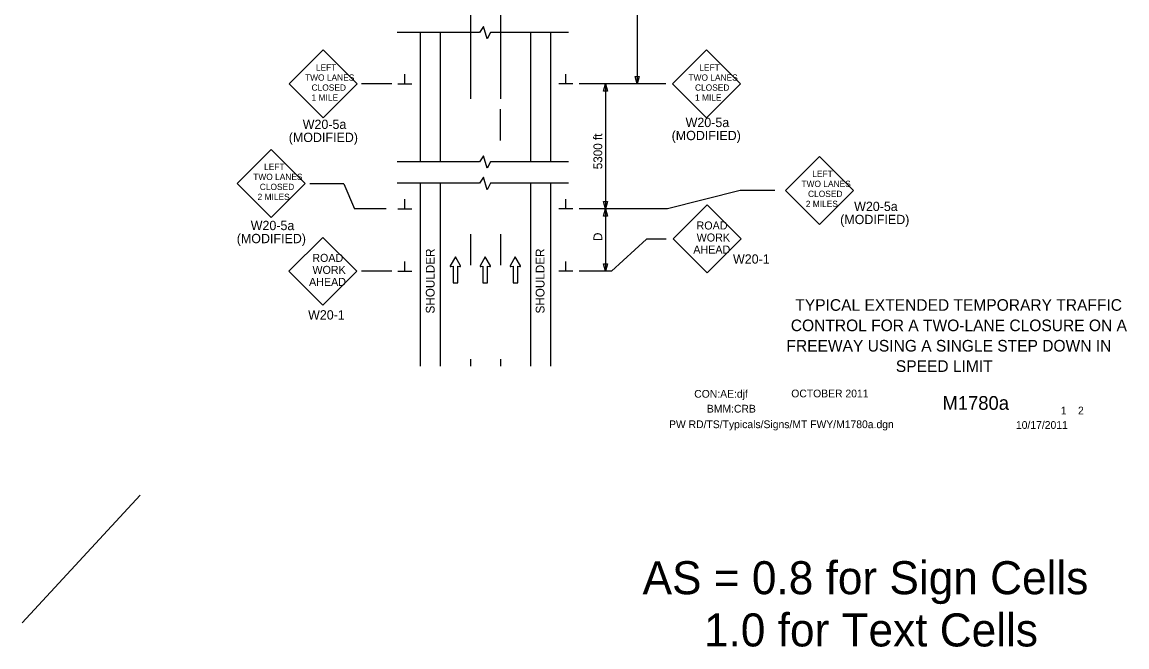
# Model space of a CAD drawing. Extents: x 16553 to 18478, y 5759 to 7026.
# Drawn here: x 16553 to 17437, y 5759 to 6259 of the extents above; entities that cross this region are included whole.
import ezdxf

# ---------------------------------------------------------------- set-up
doc = ezdxf.new("R2010")
doc.units = 0
for name, color, linetype in [('ALI_LEGAL_EX', 7, 'Continuous'), ('BORDER', 7, 'Continuous'), ('BORDER_SIGNAL_WO', 7, 'Continuous'), ('MT_SCRATCH_LEVEL_E', 7, 'Continuous'), ('PAVT_EDGE_EX', 7, 'Continuous'), ('TRAFFIC_SIGNS_PR', 7, 'Continuous'), ('TYPICAL_TEXT_DIMEN_PR', 7, 'Continuous')]:
    doc.layers.add(name, color=color, linetype=linetype)

msp = doc.modelspace()

# ---------------------------------------------------------------- linework, layer by layer
at = {"layer": 'ALI_LEGAL_EX'}
for p, q in [((16911.66, 7026.35), (16911.66, 6197.16)), ((16935.66, 7026.35), (16935.66, 6197.16)), ((16935.66, 7026.35), (16935.66, 6197.16))]:
    msp.add_line(p, q, dxfattribs=at)
for points in [[(16911.66, 6226.35), (16911.66, 6201.35)], [(16935.66, 6226.35), (16935.66, 6201.35)], [(16935.66, 6163.99), (16935.66, 6188.99)], [(16911.66, 6088.99), (16911.66, 6063.99)], [(16935.66, 6088.99), (16935.66, 6063.99)], [(16911.66, 5988.99), (16911.66, 5983.43)], [(16935.66, 5988.99), (16935.66, 5983.43)]]:
    msp.add_lwpolyline(points, dxfattribs=at)
at = {"layer": 'MT_SCRATCH_LEVEL_E'}
for p, q in [((16899.66, 6070.89), (16895.55, 6063.65)), ((16903.81, 6063.65), (16899.66, 6070.89)), ((16923.57, 6070.89), (16919.46, 6063.65)), ((16927.71, 6063.65), (16923.57, 6070.89)), ((16947.62, 6070.89), (16943.51, 6063.65)), ((16951.77, 6063.65), (16947.62, 6070.89)), ((16896.03, 6062.97), (16897.81, 6063.28)), ((16897.81, 6063.28), (16897.81, 6050.03)), ((16901.55, 6050.03), (16901.55, 6063.28)), ((16901.55, 6063.28), (16903.33, 6062.97)), ((16919.94, 6062.97), (16921.72, 6063.28)), ((16921.72, 6063.28), (16921.72, 6050.03)), ((16925.46, 6050.03), (16925.46, 6063.28)), ((16925.46, 6063.28), (16927.24, 6062.97)), ((16943.99, 6062.97), (16945.77, 6063.28)), ((16945.77, 6063.28), (16945.77, 6050.03)), ((16949.51, 6050.03), (16949.51, 6063.28)), ((16949.51, 6063.28), (16951.29, 6062.97)), ((16897.81, 6050.03), (16901.55, 6050.03)), ((16921.72, 6050.03), (16925.46, 6050.03)), ((16945.77, 6050.03), (16949.51, 6050.03))]:
    msp.add_line(p, q, dxfattribs=at)
for centre, start, end in [((16895.96, 6063.43), 150.42484, 279.96381), ((16903.4, 6063.43), 260.03619, 29.77312), ((16919.86, 6063.43), 150.42484, 279.96381), ((16927.3, 6063.43), 260.03619, 29.77312), ((16943.92, 6063.43), 150.42484, 279.96381), ((16951.36, 6063.43), 260.03619, 29.77312)]:
    msp.add_arc(centre, 0.463, start, end, dxfattribs=at)
at = {"layer": 'PAVT_EDGE_EX'}
for p, q in [((16871.66, 6250.21), (16871.66, 6146.79)), ((16887.66, 6250.21), (16887.66, 6146.8)), ((16959.66, 6250.21), (16959.66, 6146.8)), ((16975.66, 6250.21), (16975.66, 6146.8)), ((16959.66, 6226.79), (16959.66, 6223.96)), ((16871.66, 6129.66), (16871.66, 5983.43)), ((16887.66, 6129.66), (16887.66, 5983.43)), ((16959.66, 6129.66), (16959.66, 5983.43)), ((16975.66, 6129.66), (16975.66, 5983.43))]:
    msp.add_line(p, q, dxfattribs=at)
at = {"layer": 'TRAFFIC_SIGNS_PR'}
for p, q in [((16793.87, 6236.42), (16766.69, 6209.23)), ((16821.06, 6209.23), (16793.87, 6236.42)), ((17100.47, 6236.41), (17073.29, 6209.23)), ((17127.66, 6209.23), (17100.47, 6236.41)), ((16766.69, 6209.23), (16793.87, 6182.05)), ((16793.87, 6182.05), (16821.06, 6209.23)), ((17073.29, 6209.23), (17100.47, 6182.04)), ((17100.47, 6182.04), (17127.66, 6209.23)), ((16752.46, 6156.65), (16725.27, 6129.46)), ((16779.65, 6129.46), (16752.46, 6156.65)), ((17190.86, 6151.08), (17163.67, 6123.89)), ((17218.05, 6123.89), (17190.86, 6151.08)), ((16725.27, 6129.46), (16752.46, 6102.27)), ((16752.46, 6102.27), (16779.65, 6129.46)), ((17163.67, 6123.89), (17190.86, 6096.7)), ((17190.86, 6096.7), (17218.05, 6123.89)), ((17101.01, 6112.28), (17073.82, 6085.1)), ((17128.2, 6085.1), (17101.01, 6112.28)), ((16793.75, 6086.37), (16766.6, 6059.22)), ((16820.9, 6059.22), (16793.75, 6086.37)), ((17073.82, 6085.1), (17101.01, 6057.91)), ((17101.01, 6057.91), (17128.2, 6085.1)), ((16766.6, 6059.22), (16793.75, 6032.06)), ((16793.75, 6032.06), (16820.9, 6059.22))]:
    msp.add_line(p, q, dxfattribs=at)
at = {"layer": 'TYPICAL_TEXT_DIMEN_PR'}
for p, q in [((17045.1, 6561.07), (17045.1, 6209.23)), ((16922.27, 6255.01), (16919.01, 6250.21)), ((16925.01, 6245.07), (16922.27, 6255.01)), ((16919.01, 6250.21), (16853.07, 6250.21)), ((16927.75, 6250.21), (16925.01, 6245.07)), ((16990.08, 6250.21), (16927.75, 6250.21)), ((16859.29, 6209.23), (16859.29, 6217.01)), ((16988.04, 6209.23), (16988.04, 6217.01)), ((17045.1, 6209.23), (17043.53, 6215.09)), ((17043.53, 6215.09), (17045.1, 6215.09)), ((17045.1, 6215.09), (17046.67, 6215.09)), ((17046.67, 6215.09), (17045.1, 6209.23)), ((16848.86, 6209.23), (16824.56, 6209.23)), ((16853.66, 6209.23), (16864.91, 6209.23)), ((16993.66, 6209.23), (16982.41, 6209.23)), ((17067.96, 6209.23), (16998.66, 6209.23)), ((17018.09, 6203.36), (17019.66, 6209.23)), ((17019.66, 6203.36), (17018.09, 6203.36)), ((17019.66, 6209.23), (17019.66, 6109.23)), ((17019.66, 6209.23), (17021.24, 6203.36)), ((17021.24, 6203.36), (17019.66, 6203.36)), ((16922.27, 6151.59), (16919.01, 6146.79)), ((16925.01, 6141.65), (16922.27, 6151.59)), ((16919.01, 6146.79), (16853.07, 6146.79)), ((16927.75, 6146.79), (16925.01, 6141.65)), ((16990.08, 6146.79), (16927.75, 6146.79)), ((16922.27, 6134.45), (16919.01, 6129.65)), ((16925.01, 6124.51), (16922.27, 6134.45)), ((16810.37, 6129.13), (16783.2, 6129.13)), ((16810.37, 6129.13), (16819.13, 6109.23)), ((16919.01, 6129.65), (16853.07, 6129.65)), ((16927.75, 6129.65), (16925.01, 6124.51)), ((16990.08, 6129.65), (16927.75, 6129.65)), ((17127.51, 6123.89), (17069.24, 6109.23)), ((17155.1, 6123.89), (17127.51, 6123.89)), ((16859.29, 6109.23), (16859.29, 6117.01)), ((16988.04, 6109.23), (16988.04, 6117.01)), ((17019.66, 6109.23), (17018.09, 6115.09)), ((17018.09, 6115.09), (17019.66, 6115.09)), ((17019.66, 6115.09), (17021.24, 6115.09)), ((17021.24, 6115.09), (17019.66, 6109.23)), ((16844.35, 6109.23), (16819.13, 6109.23)), ((16853.66, 6109.23), (16864.91, 6109.23)), ((16993.66, 6109.23), (16982.41, 6109.23)), ((17069.24, 6109.23), (16998.66, 6109.23)), ((17018.09, 6103.36), (17019.66, 6109.23)), ((17019.66, 6109.23), (17019.66, 6059.23)), ((17019.66, 6109.23), (17021.24, 6103.36)), ((17019.66, 6103.36), (17018.09, 6103.36)), ((17021.24, 6103.36), (17019.66, 6103.36)), ((17052.49, 6085.03), (17024.66, 6059.23)), ((17068.18, 6085.03), (17052.49, 6085.03)), ((16859.29, 6059.23), (16859.29, 6067.01)), ((16988.04, 6059.23), (16988.04, 6067.01)), ((17019.66, 6059.23), (17018.09, 6065.09)), ((17018.09, 6065.09), (17019.66, 6065.09)), ((17019.66, 6065.09), (17021.24, 6065.09)), ((17021.24, 6065.09), (17019.66, 6059.23)), ((16848.86, 6059.23), (16824.56, 6059.23)), ((16853.66, 6059.23), (16864.91, 6059.23)), ((16993.66, 6059.23), (16982.41, 6059.23)), ((17024.66, 6059.23), (16998.66, 6059.23)), ((16647.75, 5880), (16553.21, 5777.94))]:
    msp.add_line(p, q, dxfattribs=at)

# ---------------------------------------------------------------- texts
at = {"layer": 'BORDER'}
for s, p in [('TYPICAL EXTENDED TEMPORARY TRAFFIC', (17171.54, 6027.6)), ('CONTROL FOR A TWO-LANE CLOSURE ON A', (17167.92, 6011.3)), ('FREEWAY USING A SINGLE STEP DOWN IN ', (17164.42, 5995)), ('SPEED LIMIT', (17251.92, 5978.7))]:
    msp.add_text(s, height=9.3, dxfattribs=at).set_placement(p)
at = {"layer": 'BORDER_SIGNAL_WO'}
for s, height, p in [('CON:AE:djf  ', 6.2, (17090.69, 5958.06)), ('    OCTOBER 2011', 6.2, (17159.08, 5958.34)), ('    M1780a   ', 11, (17272.86, 5948.38)), ('BMM:CRB', 6.2, (17100.81, 5946.17)), (' 1    2 ', 6.2, (17381.45, 5944.7)), ('PW RD/TS/Typicals/Signs/MT FWY/M1780a.dgn      ', 6.2, (17070.55, 5933.71)), ('10/17/2011', 6.2, (17347.93, 5933.13)), ('AS = 0.8 for Sign Cells', 26.4241, (17049.39, 5800.83)), ('     1.0 for Text Cells', 26.4241, (17049.39, 5759.05))]:
    msp.add_text(s, height=height, dxfattribs=at).set_placement(p)
at = {"layer": 'TRAFFIC_SIGNS_PR'}
for s, height, p in [('LEFT', 5.006, (16788.11, 6219.73)), ('LEFT', 5.006, (17094.72, 6219.72)), ('TWO LANES', 5.006, (16779.46, 6211.72)), ('TWO LANES', 5.006, (17086.07, 6211.71)), ('CLOSED', 5.006, (16784.7, 6203.71)), ('CLOSED', 5.006, (17091.3, 6203.7)), ('1 MILE', 5.006, (16784.69, 6195.7)), ('1 MILE', 5.006, (17091.3, 6195.69)), ('W20-5a', 7.449, (16777.62, 6173.09)), ('W20-5a', 7.449, (17083.79, 6174.59)), ('(MODIFIED)', 7.449, (16766.46, 6162.64)), ('(MODIFIED)', 7.449, (17072.63, 6164.14)), ('LEFT', 5.006, (16746.7, 6140.26)), ('TWO LANES', 5.006, (16738.05, 6132.25)), ('TWO LANES', 5.006, (17176.45, 6126.68)), ('LEFT', 5.006, (17185.11, 6134.69)), ('CLOSED', 5.006, (16743.28, 6124.24)), ('CLOSED', 5.006, (17181.69, 6118.67)), ('2 MILES', 5.006, (16741.53, 6116.23)), ('2 MILES', 5.006, (17179.93, 6110.66)), ('W20-5a', 7.449, (17218.55, 6107.42)), ('(MODIFIED)', 7.449, (17207.39, 6096.96)), ('W20-5a', 7.449, (16736.04, 6092.15)), ('ROAD', 6.408, (17092.54, 6092.65)), ('(MODIFIED)', 7.449, (16724.88, 6081.7)), ('WORK', 6.408, (17092.65, 6083.03)), ('AHEAD', 6.408, (17089.96, 6073.42)), ('ROAD', 6.4, (16785.29, 6066.75)), ('W20-1', 7.449, (17121.69, 6065.31)), ('WORK', 6.4, (16785.4, 6057.15)), ('AHEAD', 6.4, (16782.71, 6047.55)), ('W20-1', 7.44, (16781.92, 6020.62))]:
    msp.add_text(s, height=height, dxfattribs=at).set_placement(p)
at = {"layer": 'TYPICAL_TEXT_DIMEN_PR'}
for s, p in [('5300 ft', (17017.11, 6140.83)), ('D', (17017.11, 6083.44)), ('SHOULDER', (16883.08, 6025.44)), ('SHOULDER', (16970.94, 6025.44))]:
    msp.add_text(s, height=7, rotation=90, dxfattribs=at).set_placement(p)

doc.saveas('drawing.dxf')
